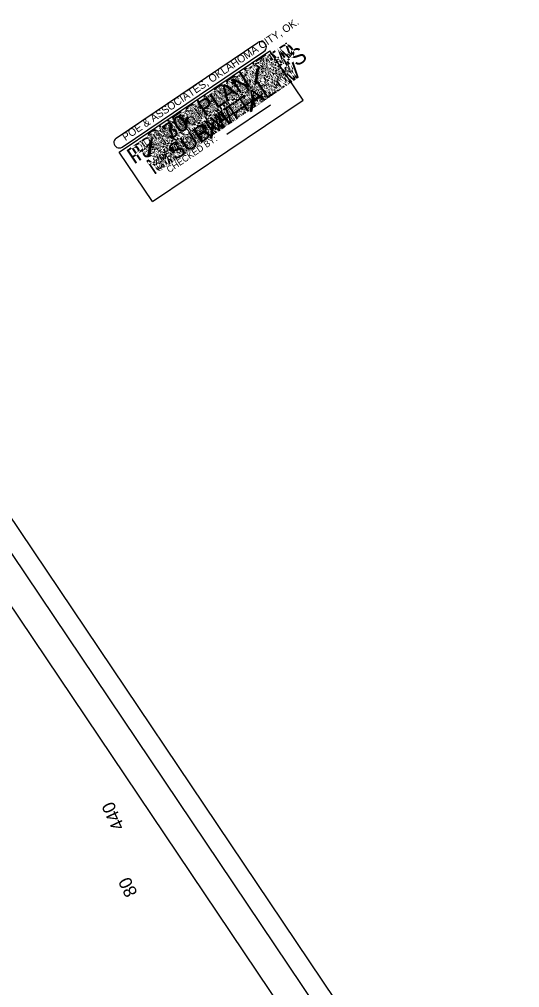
# Model space of a CAD drawing. Extents: x 2150215 to 2152378, y 141356 to 143523.
# Drawn here: x 2151915 to 2152378, y 142627 to 143523 of the extents above; entities that cross this region are included whole.
import ezdxf

# ---------------------------------------------------------------- set-up
doc = ezdxf.new("R2010")
doc.units = 0
for name, color, linetype in [('PR_Align_Ramp_B_Sta', 7, 'Continuous'), ('PR_Align_Service_D_Sta', 7, 'Continuous'), ('SHT_Plot_Shape_Full', 7, 'Continuous'), ('SHT_Plot_Shape_Half', 7, 'Continuous'), ('SHT_Sheet_Border', 7, 'Continuous'), ('SHT_Stamp_30_Submit', 7, 'Continuous'), ('SHT_Stamp_70_Submit', 7, 'Continuous'), ('SHT_Stamp_Check_Print', 7, 'Continuous'), ('SHT_Stamp_Est_Inf', 7, 'Continuous'), ('SHT_Stamp_FFR', 7, 'Continuous'), ('SHT_Stamp_Info_Material', 7, 'Continuous'), ('SHT_Stamp_No_Const', 7, 'Continuous'), ('SHT_Stamp_No_Design', 7, 'Continuous'), ('SHT_Stamp_Plan_Hand', 7, 'Continuous'), ('SHT_Stamp_Pre_Plan', 7, 'Continuous'), ('SHT_Stamp_Prop_RW', 7, 'Continuous'), ('SHT_Stamp_Ret_Sub', 7, 'Continuous'), ('SHT_Stamp_Rev_Prop_RW', 7, 'Continuous'), ('SHT_Stamp_Rev_Sheet', 7, 'Continuous'), ('SHT_Stamp_RW_Utilities_Meeting', 7, 'Continuous'), ('SHT_Stamp_RW_Utilities_Review', 7, 'Continuous'), ('SHT_Stamp_Send_Comments', 7, 'Continuous')]:
    doc.layers.add(name, color=color, linetype=linetype)

msp = doc.modelspace()

# ---------------------------------------------------------------- linework, layer by layer
at = {"layer": 'SHT_Plot_Shape_Full'}
msp.add_lwpolyline([(2150214.9, 142351.93), (2151708.05, 143357.17), (2152378.21, 142361.74), (2150885.06, 141356.5)], close=True, dxfattribs=at)
at = {"layer": 'SHT_Plot_Shape_Half'}
msp.add_lwpolyline([(2150305.85, 142363.43), (2151716.05, 143312.83), (2152330.36, 142400.35), (2150920.17, 141450.96)], close=True, dxfattribs=at)
at = {"layer": 'SHT_Sheet_Border'}
msp.add_lwpolyline([(2152293.59, 142405.73), (2150987.09, 141526.14), (2150400.7, 142397.15), (2151707.2, 143276.73)], close=True, dxfattribs=at)
at = {"layer": 'SHT_Stamp_30_Submit'}
for p, q in [((2152004.48, 143413.28), (2152135.78, 143501.68)), ((2152007.31, 143400.12), (2152146.91, 143494.1)), ((2152177.6, 143448.51), (2152146.91, 143494.1)), ((2152010.06, 143404.98), (2152141.37, 143493.38)), ((2152038, 143354.53), (2152177.6, 143448.51)), ((2152068.31, 143420.8), (2152069.95, 143432.3)), ((2152069.05, 143421.3), (2152070.69, 143432.8)), ((2152069.26, 143421.44), (2152070.89, 143432.94)), ((2152069.58, 143421.66), (2152071.22, 143433.16)), ((2152069.95, 143432.3), (2152071.22, 143433.16)), ((2152068.31, 143420.8), (2152069.58, 143421.66)), ((2152038, 143354.53), (2152007.31, 143400.12))]:
    msp.add_line(p, q, dxfattribs=at)
for centre, start, end in [((2152138.58, 143497.55), 303.94984, 123.95461), ((2152007.27, 143409.15), 123.94506, 303.94984)]:
    msp.add_arc(centre, 5, start, end, dxfattribs=at)
at = {"layer": 'SHT_Stamp_70_Submit'}
for p, q in [((2152004.48, 143413.28), (2152135.78, 143501.68)), ((2152007.31, 143400.12), (2152146.91, 143494.1)), ((2152177.6, 143448.51), (2152146.91, 143494.1)), ((2152010.06, 143404.98), (2152141.37, 143493.38)), ((2152038, 143354.53), (2152177.6, 143448.51)), ((2152068.31, 143420.8), (2152069.95, 143432.3)), ((2152069.05, 143421.3), (2152070.69, 143432.8)), ((2152069.26, 143421.44), (2152070.89, 143432.94)), ((2152069.58, 143421.66), (2152071.22, 143433.16)), ((2152069.95, 143432.3), (2152071.22, 143433.16)), ((2152068.31, 143420.8), (2152069.58, 143421.66)), ((2152038, 143354.53), (2152007.31, 143400.12))]:
    msp.add_line(p, q, dxfattribs=at)
for centre, start, end in [((2152138.58, 143497.55), 303.94984, 123.95461), ((2152007.27, 143409.15), 123.94506, 303.94984)]:
    msp.add_arc(centre, 5, start, end, dxfattribs=at)
at = {"layer": 'SHT_Stamp_Check_Print'}
for p, q in [((2152004.48, 143413.28), (2152135.78, 143501.68)), ((2152007.31, 143400.12), (2152146.91, 143494.1)), ((2152177.6, 143448.51), (2152146.91, 143494.1)), ((2152010.06, 143404.98), (2152141.37, 143493.38)), ((2152099.93, 143427.43), (2152140.17, 143454.53)), ((2152038, 143354.53), (2152177.6, 143448.51)), ((2152107.06, 143416.83), (2152147.31, 143443.93)), ((2152038, 143354.53), (2152007.31, 143400.12))]:
    msp.add_line(p, q, dxfattribs=at)
for centre, start, end in [((2152138.58, 143497.55), 303.94984, 123.95461), ((2152007.27, 143409.15), 123.94506, 303.94984)]:
    msp.add_arc(centre, 5, start, end, dxfattribs=at)
at = {"layer": 'SHT_Stamp_Est_Inf'}
for p, q in [((2152004.48, 143413.28), (2152135.78, 143501.68)), ((2152007.31, 143400.12), (2152146.91, 143494.1)), ((2152177.6, 143448.51), (2152146.91, 143494.1)), ((2152010.06, 143404.98), (2152141.37, 143493.38)), ((2152038, 143354.53), (2152177.6, 143448.51)), ((2152038, 143354.53), (2152007.31, 143400.12))]:
    msp.add_line(p, q, dxfattribs=at)
for centre, start, end in [((2152138.58, 143497.55), 303.94984, 123.95461), ((2152007.27, 143409.15), 123.94506, 303.94984)]:
    msp.add_arc(centre, 5, start, end, dxfattribs=at)
at = {"layer": 'SHT_Stamp_FFR'}
for p, q in [((2152004.48, 143413.28), (2152135.78, 143501.68)), ((2152007.31, 143400.12), (2152146.91, 143494.1)), ((2152177.6, 143448.51), (2152146.91, 143494.1)), ((2152010.06, 143404.98), (2152141.37, 143493.38)), ((2152038, 143354.53), (2152177.6, 143448.51)), ((2152038, 143354.53), (2152007.31, 143400.12))]:
    msp.add_line(p, q, dxfattribs=at)
for centre, start, end in [((2152138.58, 143497.55), 303.94984, 123.95461), ((2152007.27, 143409.15), 123.94506, 303.94984)]:
    msp.add_arc(centre, 5, start, end, dxfattribs=at)
at = {"layer": 'SHT_Stamp_Info_Material'}
for p, q in [((2152004.48, 143413.28), (2152135.78, 143501.68)), ((2152007.31, 143400.12), (2152146.91, 143494.1)), ((2152177.6, 143448.51), (2152146.91, 143494.1)), ((2152010.06, 143404.98), (2152141.37, 143493.38)), ((2152038, 143354.53), (2152177.6, 143448.51)), ((2152038, 143354.53), (2152007.31, 143400.12))]:
    msp.add_line(p, q, dxfattribs=at)
for centre, start, end in [((2152138.58, 143497.55), 303.94984, 123.95461), ((2152007.27, 143409.15), 123.94506, 303.94984)]:
    msp.add_arc(centre, 5, start, end, dxfattribs=at)
at = {"layer": 'SHT_Stamp_No_Const'}
for p, q in [((2152004.48, 143413.28), (2152135.78, 143501.68)), ((2152007.31, 143400.12), (2152146.91, 143494.1)), ((2152177.6, 143448.51), (2152146.91, 143494.1)), ((2152010.06, 143404.98), (2152141.37, 143493.38)), ((2152038, 143354.53), (2152177.6, 143448.51)), ((2152038, 143354.53), (2152007.31, 143400.12))]:
    msp.add_line(p, q, dxfattribs=at)
for centre, start, end in [((2152138.58, 143497.55), 303.94984, 123.95461), ((2152007.27, 143409.15), 123.94506, 303.94984)]:
    msp.add_arc(centre, 5, start, end, dxfattribs=at)
at = {"layer": 'SHT_Stamp_No_Design'}
for p, q in [((2152004.48, 143413.28), (2152135.78, 143501.68)), ((2152007.31, 143400.12), (2152146.91, 143494.1)), ((2152177.6, 143448.51), (2152146.91, 143494.1)), ((2152010.06, 143404.98), (2152141.37, 143493.38)), ((2152038, 143354.53), (2152177.6, 143448.51)), ((2152038, 143354.53), (2152007.31, 143400.12))]:
    msp.add_line(p, q, dxfattribs=at)
for centre, start, end in [((2152138.58, 143497.55), 303.94984, 123.95461), ((2152007.27, 143409.15), 123.94506, 303.94984)]:
    msp.add_arc(centre, 5, start, end, dxfattribs=at)
at = {"layer": 'SHT_Stamp_Plan_Hand'}
for p, q in [((2152004.48, 143413.28), (2152135.78, 143501.68)), ((2152007.31, 143400.12), (2152146.91, 143494.1)), ((2152177.6, 143448.51), (2152146.91, 143494.1)), ((2152010.06, 143404.98), (2152141.37, 143493.38)), ((2152038, 143354.53), (2152177.6, 143448.51)), ((2152038, 143354.53), (2152007.31, 143400.12))]:
    msp.add_line(p, q, dxfattribs=at)
for centre, start, end in [((2152138.58, 143497.55), 303.94984, 123.95461), ((2152007.27, 143409.15), 123.94506, 303.94984)]:
    msp.add_arc(centre, 5, start, end, dxfattribs=at)
at = {"layer": 'SHT_Stamp_Pre_Plan'}
for p, q in [((2152004.48, 143413.28), (2152135.78, 143501.68)), ((2152007.31, 143400.12), (2152146.91, 143494.1)), ((2152177.6, 143448.51), (2152146.91, 143494.1)), ((2152010.06, 143404.98), (2152141.37, 143493.38)), ((2152038, 143354.53), (2152177.6, 143448.51)), ((2152038, 143354.53), (2152007.31, 143400.12))]:
    msp.add_line(p, q, dxfattribs=at)
for centre, start, end in [((2152138.58, 143497.55), 303.94984, 123.95461), ((2152007.27, 143409.15), 123.94506, 303.94984)]:
    msp.add_arc(centre, 5, start, end, dxfattribs=at)
at = {"layer": 'SHT_Stamp_Prop_RW'}
for p, q in [((2152004.48, 143413.28), (2152135.78, 143501.68)), ((2152007.31, 143400.12), (2152146.91, 143494.1)), ((2152177.6, 143448.51), (2152146.91, 143494.1)), ((2152010.06, 143404.98), (2152141.37, 143493.38)), ((2152038, 143354.53), (2152177.6, 143448.51)), ((2152091.77, 143413.14), (2152093.79, 143427.34)), ((2152092.69, 143413.75), (2152094.7, 143427.95)), ((2152092.94, 143413.93), (2152094.96, 143428.12)), ((2152093.34, 143414.19), (2152095.36, 143428.39)), ((2152093.79, 143427.34), (2152095.36, 143428.39)), ((2152091.77, 143413.14), (2152093.34, 143414.19)), ((2152038, 143354.53), (2152007.31, 143400.12))]:
    msp.add_line(p, q, dxfattribs=at)
for centre, start, end in [((2152138.58, 143497.55), 303.94984, 123.95461), ((2152007.27, 143409.15), 123.94506, 303.94984)]:
    msp.add_arc(centre, 5, start, end, dxfattribs=at)
at = {"layer": 'SHT_Stamp_Ret_Sub'}
for p, q in [((2152004.48, 143413.28), (2152135.78, 143501.68)), ((2152007.31, 143400.12), (2152146.91, 143494.1)), ((2152177.6, 143448.51), (2152146.91, 143494.1)), ((2152010.06, 143404.98), (2152141.37, 143493.38)), ((2152038, 143354.53), (2152177.6, 143448.51)), ((2152038, 143354.53), (2152007.31, 143400.12))]:
    msp.add_line(p, q, dxfattribs=at)
for centre, start, end in [((2152138.58, 143497.55), 303.94984, 123.95461), ((2152007.27, 143409.15), 123.94506, 303.94984)]:
    msp.add_arc(centre, 5, start, end, dxfattribs=at)
at = {"layer": 'SHT_Stamp_Rev_Prop_RW'}
for p, q in [((2152004.48, 143413.28), (2152135.78, 143501.68)), ((2152007.31, 143400.12), (2152146.91, 143494.1)), ((2152177.6, 143448.51), (2152146.91, 143494.1)), ((2152010.06, 143404.98), (2152141.37, 143493.38)), ((2152128.77, 143437.88), (2152130.79, 143452.08)), ((2152129.69, 143438.49), (2152131.7, 143452.69)), ((2152129.94, 143438.67), (2152131.96, 143452.86)), ((2152130.34, 143438.93), (2152132.36, 143453.13)), ((2152130.79, 143452.08), (2152132.36, 143453.13)), ((2152038, 143354.53), (2152177.6, 143448.51)), ((2152128.77, 143437.88), (2152130.34, 143438.93)), ((2152038, 143354.53), (2152007.31, 143400.12))]:
    msp.add_line(p, q, dxfattribs=at)
for centre, start, end in [((2152138.58, 143497.55), 303.94984, 123.95461), ((2152007.27, 143409.15), 123.94506, 303.94984)]:
    msp.add_arc(centre, 5, start, end, dxfattribs=at)
at = {"layer": 'SHT_Stamp_Rev_Sheet'}
for p, q in [((2152004.48, 143413.28), (2152135.78, 143501.68)), ((2152007.31, 143400.12), (2152146.91, 143494.1)), ((2152177.6, 143448.51), (2152146.91, 143494.1)), ((2152010.06, 143404.98), (2152141.37, 143493.38)), ((2152038, 143354.53), (2152177.6, 143448.51)), ((2152038, 143354.53), (2152007.31, 143400.12))]:
    msp.add_line(p, q, dxfattribs=at)
for centre, start, end in [((2152138.58, 143497.55), 303.94984, 123.95461), ((2152007.27, 143409.15), 123.94506, 303.94984)]:
    msp.add_arc(centre, 5, start, end, dxfattribs=at)
at = {"layer": 'SHT_Stamp_RW_Utilities_Meeting'}
for p, q in [((2152004.48, 143413.28), (2152135.78, 143501.68)), ((2152007.31, 143400.12), (2152146.91, 143494.1)), ((2152177.6, 143448.51), (2152146.91, 143494.1)), ((2152010.06, 143404.98), (2152141.37, 143493.38)), ((2152038, 143354.53), (2152177.6, 143448.51)), ((2152034.05, 143396.39), (2152036.06, 143410.59)), ((2152034.96, 143397), (2152036.97, 143411.2)), ((2152035.22, 143397.17), (2152037.23, 143411.37)), ((2152035.61, 143397.44), (2152037.63, 143411.64)), ((2152036.06, 143410.59), (2152037.63, 143411.64)), ((2152038, 143354.53), (2152007.31, 143400.12)), ((2152034.05, 143396.39), (2152035.61, 143397.44))]:
    msp.add_line(p, q, dxfattribs=at)
for centre, start, end in [((2152138.58, 143497.55), 303.94984, 123.95461), ((2152007.27, 143409.15), 123.94506, 303.94984)]:
    msp.add_arc(centre, 5, start, end, dxfattribs=at)
at = {"layer": 'SHT_Stamp_RW_Utilities_Review'}
for p, q in [((2152004.48, 143413.28), (2152135.78, 143501.68)), ((2152007.31, 143400.12), (2152146.91, 143494.1)), ((2152177.6, 143448.51), (2152146.91, 143494.1)), ((2152010.06, 143404.98), (2152141.37, 143493.38)), ((2152133.12, 143463.09), (2152135.14, 143477.29)), ((2152134.04, 143463.7), (2152136.05, 143477.9)), ((2152134.29, 143463.88), (2152136.31, 143478.07)), ((2152134.69, 143464.15), (2152136.71, 143478.34)), ((2152135.14, 143477.29), (2152136.71, 143478.34)), ((2152133.12, 143463.09), (2152134.69, 143464.15)), ((2152038, 143354.53), (2152177.6, 143448.51)), ((2152038, 143354.53), (2152007.31, 143400.12))]:
    msp.add_line(p, q, dxfattribs=at)
for centre, start, end in [((2152138.58, 143497.55), 303.94984, 123.95461), ((2152007.27, 143409.15), 123.94506, 303.94984)]:
    msp.add_arc(centre, 5, start, end, dxfattribs=at)
at = {"layer": 'SHT_Stamp_Send_Comments'}
for p, q in [((2152004.48, 143413.28), (2152135.78, 143501.68)), ((2152007.31, 143400.12), (2152146.91, 143494.1)), ((2152177.6, 143448.51), (2152146.91, 143494.1)), ((2152010.06, 143404.98), (2152141.37, 143493.38)), ((2152038, 143354.53), (2152177.6, 143448.51)), ((2152038, 143354.53), (2152007.31, 143400.12))]:
    msp.add_line(p, q, dxfattribs=at)
for centre, start, end in [((2152138.58, 143497.55), 303.94984, 123.95461), ((2152007.27, 143409.15), 123.94506, 303.94984)]:
    msp.add_arc(centre, 5, start, end, dxfattribs=at)

# ---------------------------------------------------------------- texts
at = {"layer": 'PR_Align_Ramp_B_Sta'}
msp.add_text('440', height=12, rotation=114.85292, dxfattribs=at).set_placement((2152012.64, 142775.82))
at = {"layer": 'PR_Align_Service_D_Sta'}
msp.add_text('80', height=12, rotation=116.22378, dxfattribs=at).set_placement((2152024.53, 142714.42))
at = {"layer": 'SHT_Stamp_30_Submit'}
for s, height, p in [('POE & ASSOCIATES, OKLAHOMA CITY, OK.', 7, (2152013.02, 143410.44)), ('30   PLAN', 15, (2152054.28, 143411.13)), ('SUBMITTAL', 15, (2152059.08, 143392.26)), ('O', 7.65, (2152064.52, 143423.36)), ('O', 7.65, (2152073.17, 143424.11))]:
    msp.add_text(s, height=height, rotation=33.94984, dxfattribs=at).set_placement(p)
at = {"layer": 'SHT_Stamp_70_Submit'}
for s, height, p in [('POE & ASSOCIATES, OKLAHOMA CITY, OK.', 7, (2152013.02, 143410.44)), ('70   PLAN', 15, (2152053.99, 143410.93)), ('SUBMITTAL', 15, (2152059.08, 143392.26)), ('O', 7.65, (2152064.52, 143423.36)), ('O', 7.65, (2152073.17, 143424.11))]:
    msp.add_text(s, height=height, rotation=33.94984, dxfattribs=at).set_placement(p)
at = {"layer": 'SHT_Stamp_Check_Print'}
for s, height, p in [('POE & ASSOCIATES, OKLAHOMA CITY, OK.', 7, (2152013.02, 143410.45)), ('CHECK PRINT', 15, (2152038.57, 143403.17)), ('REVISED BY:', 6, (2152046.52, 143391.46)), ('CHECKED BY:', 6, (2152053.64, 143380.88))]:
    msp.add_text(s, height=height, rotation=33.94984, dxfattribs=at).set_placement(p)
at = {"layer": 'SHT_Stamp_Est_Inf'}
for s, height, p in [('POE & ASSOCIATES, OKLAHOMA CITY, OK.', 7, (2152013.02, 143410.45)), ('BASED ON EST.', 15, (2152034.73, 143397.97)), ('INFORMATION', 15, (2152050.02, 143386.16))]:
    msp.add_text(s, height=height, rotation=33.94984, dxfattribs=at).set_placement(p)
at = {"layer": 'SHT_Stamp_FFR'}
for s, height, p in [('POE & ASSOCIATES, OKLAHOMA CITY, OK.', 7, (2152013.02, 143410.45)), ('FINAL FIELD', 15, (2152043.89, 143404.13)), ('REVIEW', 15, (2152071.87, 143400.87))]:
    msp.add_text(s, height=height, rotation=33.94984, dxfattribs=at).set_placement(p)
at = {"layer": 'SHT_Stamp_Info_Material'}
for s, height, p in [('POE & ASSOCIATES, OKLAHOMA CITY, OK.', 7, (2152013.02, 143410.45)), ('INFORMATION', 15, (2152039.78, 143401.36)), ('MATERIAL ONLY', 15, (2152039.29, 143378.93))]:
    msp.add_text(s, height=height, rotation=33.94984, dxfattribs=at).set_placement(p)
at = {"layer": 'SHT_Stamp_No_Const'}
for s, height, p in [('POE & ASSOCIATES, OKLAHOMA CITY, OK.', 7, (2152013.02, 143410.45)), ('NOT TO BE USED', 15, (2152026.85, 143392.66)), ('FOR CONST.', 15, (2152057.41, 143391.14))]:
    msp.add_text(s, height=height, rotation=33.94984, dxfattribs=at).set_placement(p)
at = {"layer": 'SHT_Stamp_No_Design'}
for s, height, p in [('POE & ASSOCIATES, OKLAHOMA CITY, OK.', 7, (2152013.02, 143410.45)), ('NOT TO BE USED', 15, (2152026.85, 143392.66)), ('FOR DESIGN', 15, (2152056.68, 143390.64))]:
    msp.add_text(s, height=height, rotation=33.94984, dxfattribs=at).set_placement(p)
at = {"layer": 'SHT_Stamp_Plan_Hand'}
for s, height, p in [('POE & ASSOCIATES, OKLAHOMA CITY, OK.', 7, (2152013.02, 143410.45)), ('PLAN-IN-HAND', 15, (2152042.06, 143391.85))]:
    msp.add_text(s, height=height, rotation=33.94984, dxfattribs=at).set_placement(p)
at = {"layer": 'SHT_Stamp_Pre_Plan'}
for s, height, p in [('POE & ASSOCIATES, OKLAHOMA CITY, OK.', 7, (2152013.02, 143410.45)), ('PRELIMINARY', 15, (2152040.42, 143401.79)), ('PLANS', 15, (2152075.83, 143403.54))]:
    msp.add_text(s, height=height, rotation=33.94984, dxfattribs=at).set_placement(p)
at = {"layer": 'SHT_Stamp_Prop_RW'}
for s, height, p in [('POE & ASSOCIATES, OKLAHOMA CITY, OK.', 7, (2152013.02, 143410.45)), ('PROPOSED', 15, (2152054.57, 143411.32)), ('R W', 15, (2152082.74, 143408.19))]:
    msp.add_text(s, height=height, rotation=33.94984, dxfattribs=at).set_placement(p)
at = {"layer": 'SHT_Stamp_Ret_Sub'}
for s, height, p in [('POE & ASSOCIATES, OKLAHOMA CITY, OK.', 7, (2152013.02, 143410.45)), ('RET. SUBMITTED', 15, (2152034.19, 143397.6)), ('MATERIALS', 15, (2152058.59, 143391.93))]:
    msp.add_text(s, height=height, rotation=33.94984, dxfattribs=at).set_placement(p)
at = {"layer": 'SHT_Stamp_Rev_Prop_RW'}
for s, height, p in [('POE & ASSOCIATES, OKLAHOMA CITY, OK.', 7, (2152013.02, 143410.45)), ('PROPOSED R W', 15, (2152045.8, 143383.32)), ('REVISED', 15, (2152059.86, 143414.89))]:
    msp.add_text(s, height=height, rotation=33.94984, dxfattribs=at).set_placement(p)
at = {"layer": 'SHT_Stamp_Rev_Sheet'}
for s, height, p in [('POE & ASSOCIATES, OKLAHOMA CITY, OK.', 7, (2152013.02, 143410.45)), ('REVISED SHEET', 15, (2152040, 143390.46))]:
    msp.add_text(s, height=height, rotation=33.94984, dxfattribs=at).set_placement(p)
at = {"layer": 'SHT_Stamp_RW_Utilities_Meeting'}
for s, height, p in [('POE & ASSOCIATES, OKLAHOMA CITY, OK.', 7, (2152013.02, 143410.44)), ('R W & UTILITIES', 15, (2152024.94, 143391.37)), ('MEETING', 15, (2152067.07, 143397.63))]:
    msp.add_text(s, height=height, rotation=33.94984, dxfattribs=at).set_placement(p)
at = {"layer": 'SHT_Stamp_RW_Utilities_Review'}
for s, height, p in [('POE & ASSOCIATES, OKLAHOMA CITY, OK.', 7, (2152013.02, 143410.44)), ('PRELIMINARY R W', 15, (2152020.97, 143388.7)), ('& UTIL.  REVIEW', 15, (2152042.96, 143381.41))]:
    msp.add_text(s, height=height, rotation=33.94984, dxfattribs=at).set_placement(p)
at = {"layer": 'SHT_Stamp_Send_Comments'}
for s, height, p in [('POE & ASSOCIATES, OKLAHOMA CITY, OK.', 7, (2152013.02, 143410.45)), ('SEND COMMENTS', 15, (2152034.66, 143386.87))]:
    msp.add_text(s, height=height, rotation=33.94984, dxfattribs=at).set_placement(p)

doc.saveas('drawing.dxf')
